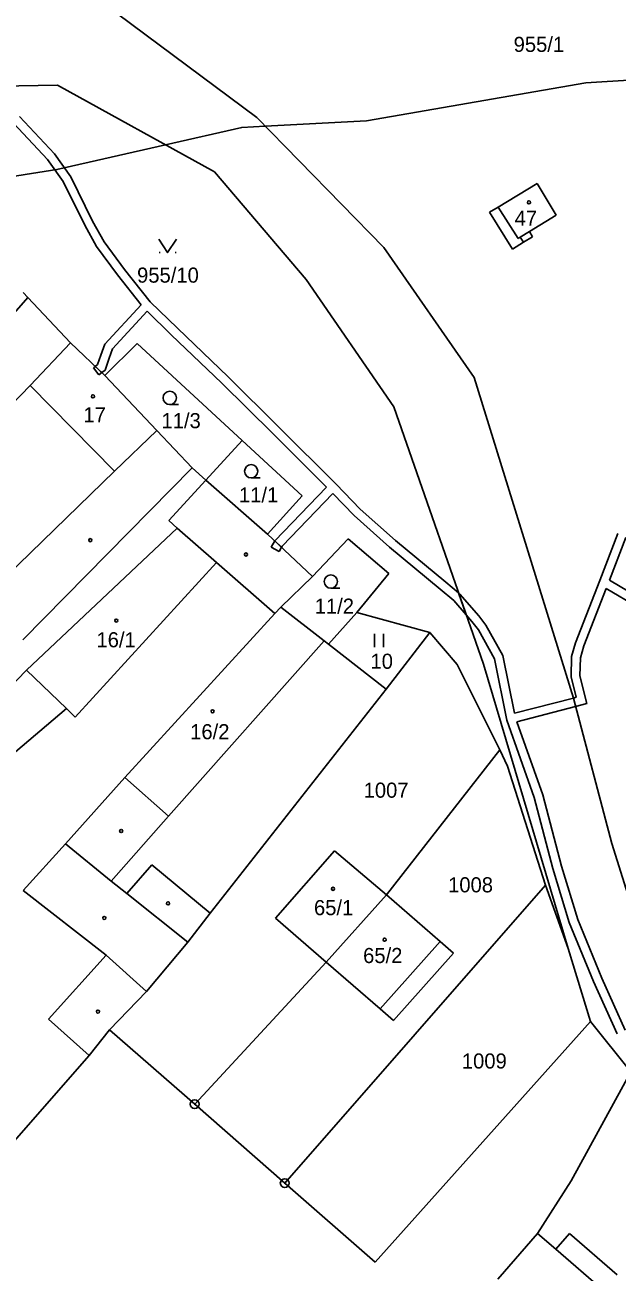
# Model space of a CAD drawing. Extents: x -749173 to -746119, y -1132678 to -1130338.
# Drawn here: x -747893.8 to -747827.1, y -1131098.8 to -1130958.5 of the extents above; entities that cross this region are included whole.
import ezdxf

# ---------------------------------------------------------------- set-up
doc = ezdxf.new("R2010")
doc.units = 0
for name, color, linetype in [('Vrstva 1', 7, 'Continuous'), ('Vrstva 18', 7, 'Continuous'), ('Vrstva 19', 7, 'Continuous'), ('Vrstva 24', 7, 'Continuous'), ('Vrstva 25', 7, 'Continuous'), ('Vrstva 3', 7, 'Continuous'), ('Vrstva 30', 7, 'Continuous'), ('Vrstva 37', 7, 'Continuous'), ('Vrstva 4', 7, 'Continuous'), ('Vrstva 52', 7, 'Continuous')]:
    doc.layers.add(name, color=color, linetype=linetype)

msp = doc.modelspace()

# ---------------------------------------------------------------- linework, layer by layer
at = {"layer": 'Vrstva 1'}
for p, q in [((-747856.43, -1131024.62), (-747848.2, -1131026.86)), ((-747848.2, -1131026.86), (-747853.12, -1131033.24)), ((-747848.2, -1131026.86), (-747845.11, -1131030.47)), ((-747853.12, -1131033.24), (-747859.61, -1131028.15)), ((-747845.11, -1131030.47), (-747840.33, -1131040.05)), ((-747842.17, -1131030.42), (-747832.63, -1131062.43)), ((-747853.12, -1131033.24), (-747872.94, -1131058.46)), ((-747853.09, -1131056.39), (-747840.33, -1131040.05)), ((-747840.33, -1131040.05), (-747839.47, -1131041.9)), ((-747839.47, -1131041.9), (-747835.16, -1131055.31)), ((-747865.56, -1131059.01), (-747858.92, -1131051.41)), ((-747858.92, -1131051.41), (-747853.09, -1131056.39)), ((-747835.16, -1131055.31), (-747864.53, -1131088.83)), ((-747835.16, -1131055.31), (-747832.63, -1131062.43)), ((-747859.86, -1131063.94), (-747853.09, -1131056.39)), ((-747853.09, -1131056.39), (-747847.05, -1131061.64)), ((-747859.86, -1131063.94), (-747865.56, -1131059.01)), ((-747847.05, -1131061.64), (-747845.55, -1131062.96)), ((-747832.63, -1131062.43), (-747830.09, -1131070.64)), ((-747874.67, -1131079.94), (-747859.86, -1131063.94)), ((-747853.8, -1131069.21), (-747859.86, -1131063.94)), ((-747845.55, -1131062.96), (-747852.29, -1131070.52)), ((-747884.28, -1131071.56), (-747880.08, -1131067.26)), ((-747852.29, -1131070.52), (-747853.8, -1131069.21)), ((-747830.09, -1131070.64), (-747854.37, -1131097.71)), ((-747830.09, -1131070.64), (-747825.56, -1131076.31)), ((-747884.28, -1131071.56), (-747886.56, -1131074.48)), ((-747874.67, -1131079.94), (-747884.28, -1131071.56)), ((-747864.53, -1131088.83), (-747874.67, -1131079.94)), ((-747854.37, -1131097.71), (-747864.53, -1131088.83))]:
    msp.add_line(p, q, dxfattribs=at)
for points in [[(-747883.35, -1130957.23), (-747867.68, -1130968.89)], [(-747905.36, -1130965.53), (-747890.11, -1130965.25)], [(-747872.45, -1130974.99), (-747890.11, -1130965.25)], [(-747867.68, -1130968.89), (-747853.38, -1130983.52)], [(-747862.12, -1130987.14), (-747872.45, -1130974.99)], [(-747836.13, -1130976.33), (-747840.51, -1130978.98)], [(-747833.96, -1130979.87), (-747836.13, -1130976.33)], [(-747840.51, -1130978.98), (-747841.46, -1130979.55)], [(-747841.46, -1130979.55), (-747838.9, -1130983.72)], [(-747836.99, -1130981.73), (-747833.96, -1130979.87)], [(-747836.63, -1130982.32), (-747837.64, -1130982.94)], [(-747836.99, -1130981.73), (-747836.63, -1130982.32)], [(-747853.38, -1130983.52), (-747843.2, -1130998.16)], [(-747837.64, -1130982.94), (-747838.9, -1130983.72)], [(-747852.24, -1131001.44), (-747862.12, -1130987.14)], [(-747893.47, -1130989.15), (-747907.26, -1131004.91)], [(-747893.98, -1130988.57), (-747893.47, -1130989.15)], [(-747893.47, -1130989.15), (-747888.65, -1130994.25)], [(-747888.65, -1130994.25), (-747884.79, -1130997.93)], [(-747884.79, -1130997.93), (-747881.15, -1130994.34)], [(-747881.15, -1130994.34), (-747869.31, -1131005.23)], [(-747878.95, -1131004.11), (-747884.79, -1130997.93)], [(-747843.2, -1130998.16), (-747832.03, -1131034.24)], [(-747842.17, -1131030.42), (-747852.24, -1131001.44)], [(-747874.96, -1131008.33), (-747878.95, -1131004.11)], [(-747869.31, -1131005.23), (-747873.4, -1131009.7)], [(-747869.31, -1131005.23), (-747862.56, -1131011.46)], [(-747874.96, -1131008.33), (-747894.04, -1131027.67)], [(-747874.96, -1131008.33), (-747873.4, -1131009.7)], [(-747873.4, -1131009.7), (-747877.57, -1131014.25)], [(-747873.4, -1131009.7), (-747866.49, -1131015.77)], [(-747862.56, -1131011.46), (-747866.49, -1131015.77)], [(-747893.59, -1131031.09), (-747876.64, -1131015.12)], [(-747877.57, -1131014.25), (-747876.64, -1131015.12)], [(-747866.49, -1131015.77), (-747861.39, -1131020.56)], [(-747861.39, -1131020.56), (-747857.4, -1131016.33)], [(-747857.4, -1131016.33), (-747852.82, -1131020.21)], [(-747861.39, -1131020.56), (-747864.99, -1131024.01)], [(-747852.82, -1131020.21), (-747856.43, -1131024.62)], [(-747865.63, -1131024.71), (-747882.52, -1131043.19)], [(-747864.99, -1131024.01), (-747865.63, -1131024.71)], [(-747860.09, -1131027.78), (-747864.99, -1131024.01)], [(-747856.43, -1131024.62), (-747859.61, -1131028.15)], [(-747859.61, -1131028.15), (-747860.09, -1131027.78)], [(-747893.59, -1131031.09), (-747905.46, -1131043.33)], [(-747832.03, -1131034.24), (-747827.69, -1131050.62)], [(-747882.52, -1131043.19), (-747889.22, -1131050.64)], [(-747889.22, -1131050.64), (-747893.98, -1131055.9)], [(-747827.69, -1131050.62), (-747823.07, -1131065.32)], [(-747884.64, -1131063.16), (-747893.98, -1131055.9)], [(-747875.44, -1131061.71), (-747872.94, -1131058.46)], [(-747875.44, -1131061.71), (-747880.08, -1131067.26)], [(-747884.64, -1131063.16), (-747891.12, -1131070.38)], [(-747891.12, -1131070.38), (-747886.56, -1131074.48)], [(-747886.56, -1131074.48), (-747913.2, -1131104.85)], [(-747832.27, -1131088.57), (-747825.56, -1131076.31)], [(-747836.06, -1131094.48), (-747832.27, -1131088.57)], [(-747840.55, -1131099.64), (-747836.06, -1131094.48)], [(-747836.06, -1131094.48), (-747834.02, -1131096.25)], [(-747834.02, -1131096.25), (-747832.48, -1131094.48)], [(-747832.48, -1131094.48), (-747827.12, -1131099.14)]]:
    msp.add_lwpolyline(points, dxfattribs=at)
at = {"layer": 'Vrstva 24'}
for p, q in [((-747874.72, -1131079.94), (-747874.62, -1131079.94)), ((-747864.58, -1131088.83), (-747864.48, -1131088.83))]:
    msp.add_line(p, q, dxfattribs=at)
for centre in [(-747874.67, -1131079.94), (-747864.53, -1131088.83)]:
    msp.add_circle(centre, 0.499, dxfattribs=at)
at = {"layer": 'Vrstva 25'}
for p, q in [((-747878.67, -1130984.09), (-747878.57, -1130984.09)), ((-747876.87, -1130984.09), (-747876.77, -1130984.09)), ((-747877.48, -1131001.2), (-747876.48, -1131001.2)), ((-747868.31, -1131009.46), (-747867.31, -1131009.46)), ((-747859.34, -1131021.87), (-747858.34, -1131021.87)), ((-747854.42, -1131027.02), (-747854.42, -1131028.52)), ((-747853.42, -1131028.52), (-747853.42, -1131027.02))]:
    msp.add_line(p, q, dxfattribs=at)
msp.add_lwpolyline([(-747878.72, -1130982.59), (-747877.72, -1130984.09), (-747876.72, -1130982.59)], dxfattribs=at)
for centre, radius in [((-747837.04, -1130978.44), 0.175), ((-747877.48, -1131000.45), 0.75), ((-747886.13, -1131000.28), 0.175), ((-747868.31, -1131008.71), 0.75), ((-747886.43, -1131016.46), 0.175), ((-747868.9, -1131018.08), 0.175), ((-747859.34, -1131021.12), 0.75), ((-747883.5, -1131025.51), 0.175), ((-747872.66, -1131035.72), 0.175), ((-747882.95, -1131049.2), 0.175), ((-747859.09, -1131055.7), 0.175), ((-747877.67, -1131057.34), 0.175), ((-747884.85, -1131058.98), 0.175), ((-747853.29, -1131061.43), 0.175), ((-747885.56, -1131069.52), 0.175)]:
    msp.add_circle(centre, radius, dxfattribs=at)
at = {"layer": 'Vrstva 3'}
for points in [[(-747836.13, -1130976.33), (-747840.51, -1130978.98)], [(-747833.96, -1130979.87), (-747836.13, -1130976.33)], [(-747840.51, -1130978.98), (-747838.26, -1130982.51)], [(-747836.99, -1130981.73), (-747833.96, -1130979.87)], [(-747838.26, -1130982.51), (-747838.01, -1130982.35)], [(-747838.01, -1130982.35), (-747836.99, -1130981.73)], [(-747893.21, -1130999.04), (-747888.65, -1130994.25)], [(-747888.65, -1130994.25), (-747884.79, -1130997.93)], [(-747878.95, -1131004.11), (-747884.79, -1130997.93)], [(-747883.69, -1131008.71), (-747893.21, -1130999.04)], [(-747883.69, -1131008.71), (-747878.95, -1131004.11)], [(-747893.59, -1131031.09), (-747876.64, -1131015.12)], [(-747876.64, -1131015.12), (-747872.21, -1131018.98)], [(-747872.21, -1131018.98), (-747888.12, -1131036.37)], [(-747865.63, -1131024.71), (-747882.52, -1131043.19)], [(-747864.99, -1131024.01), (-747865.63, -1131024.71)], [(-747860.09, -1131027.78), (-747864.99, -1131024.01)], [(-747860.09, -1131027.78), (-747877.61, -1131047.54)], [(-747889.12, -1131035.41), (-747893.59, -1131031.09)], [(-747888.12, -1131036.37), (-747889.12, -1131035.41)], [(-747882.52, -1131043.19), (-747877.61, -1131047.54)], [(-747865.56, -1131059.01), (-747858.92, -1131051.41)], [(-747858.92, -1131051.41), (-747853.09, -1131056.39)], [(-747859.86, -1131063.94), (-747853.09, -1131056.39)], [(-747859.86, -1131063.94), (-747853.09, -1131056.39)], [(-747853.09, -1131056.39), (-747847.05, -1131061.64)], [(-747859.86, -1131063.94), (-747865.56, -1131059.01)], [(-747853.8, -1131069.21), (-747847.05, -1131061.64)], [(-747853.8, -1131069.21), (-747859.86, -1131063.94)]]:
    msp.add_lwpolyline(points, dxfattribs=at)
at = {"layer": 'Vrstva 30'}
for points in [[(-747894.38, -1130968.79), (-747890.46, -1130972.99)], [(-747891.24, -1130973.63), (-747895.06, -1130969.53)], [(-747890.46, -1130972.99), (-747888.61, -1130975.57)], [(-747889.47, -1130976.09), (-747891.24, -1130973.63)], [(-747888.61, -1130975.57), (-747886.17, -1130980.56)], [(-747887.05, -1130981.02), (-747889.47, -1130976.09)], [(-747885.72, -1130983.42), (-747887.05, -1130981.02)], [(-747886.17, -1130980.56), (-747884.88, -1130982.88)], [(-747884.88, -1130982.88), (-747882.58, -1130986.01)], [(-747883.38, -1130986.61), (-747885.72, -1130983.42)], [(-747880.71, -1130989.97), (-747883.38, -1130986.61)], [(-747882.58, -1130986.01), (-747879.68, -1130989.65)], [(-747879.68, -1130989.65), (-747876.61, -1130992.62)], [(-747884.77, -1130994.4), (-747880.71, -1130989.97)], [(-747880.03, -1130990.7), (-747883.91, -1130994.94)], [(-747877.31, -1130993.34), (-747880.03, -1130990.7)], [(-747876.61, -1130992.62), (-747870.9, -1130998.07)], [(-747871.6, -1130998.79), (-747877.31, -1130993.34)], [(-747885.23, -1130995.63), (-747884.77, -1130994.4)], [(-747883.91, -1130994.94), (-747884.29, -1130995.97)], [(-747886.07, -1130997.06), (-747885.87, -1130996.9)], [(-747885.87, -1130996.9), (-747885.61, -1130996.71)], [(-747885.87, -1130996.9), (-747885.13, -1130997.6)], [(-747885.13, -1130997.6), (-747885.87, -1130996.9)], [(-747885.61, -1130996.71), (-747885.23, -1130995.63)], [(-747884.29, -1130995.97), (-747884.75, -1130997.33)], [(-747885.48, -1130997.86), (-747886.07, -1130997.06)], [(-747885.13, -1130997.6), (-747885.48, -1130997.86)], [(-747884.75, -1130997.33), (-747885.13, -1130997.6)], [(-747870.9, -1130998.07), (-747865.18, -1131003.76)], [(-747865.88, -1131004.46), (-747871.6, -1130998.79)], [(-747865.18, -1131003.76), (-747858.76, -1131010.15)], [(-747859.82, -1131010.51), (-747865.88, -1131004.46)], [(-747865.66, -1131016.55), (-747859.82, -1131010.51)], [(-747858.76, -1131010.15), (-747856.03, -1131012.96)], [(-747859.12, -1131011.22), (-747864.83, -1131017.12)], [(-747856.71, -1131013.68), (-747859.12, -1131011.22)], [(-747852.74, -1131017.26), (-747856.71, -1131013.68)], [(-747856.03, -1131012.96), (-747852.08, -1131016.5)], [(-747866.05, -1131017.26), (-747865.66, -1131016.55)], [(-747865.66, -1131016.55), (-747864.91, -1131017.26)], [(-747864.91, -1131017.26), (-747865.66, -1131016.55)], [(-747852.08, -1131016.5), (-747846.39, -1131021.2)], [(-747829.04, -1131021), (-747827.02, -1131015.71)], [(-747826.12, -1131016.15), (-747827.96, -1131020.96)], [(-747865.17, -1131017.74), (-747866.05, -1131017.26)], [(-747864.91, -1131017.26), (-747865.17, -1131017.74)], [(-747864.83, -1131017.12), (-747864.91, -1131017.26)], [(-747847.03, -1131021.98), (-747852.74, -1131017.26)], [(-747845.5, -1131023.24), (-747847.03, -1131021.98)], [(-747846.39, -1131021.2), (-747844.96, -1131022.4)], [(-747831.79, -1131028.02), (-747829.04, -1131021)], [(-747828.33, -1131021.91), (-747830.85, -1131028.34)], [(-747821.21, -1131026.12), (-747828.33, -1131021.91)], [(-747827.96, -1131020.96), (-747820.69, -1131025.26)], [(-747844.1, -1131024.86), (-747845.5, -1131023.24)], [(-747844.96, -1131022.4), (-747844.8, -1131022.53)], [(-747844.1, -1131024.86), (-747844.96, -1131022.4)], [(-747844.96, -1131022.4), (-747844.1, -1131024.86)], [(-747844.8, -1131022.53), (-747842.68, -1131024.98)], [(-747843.46, -1131025.6), (-747844.1, -1131024.86)], [(-747842.68, -1131024.98), (-747841.89, -1131026.02)], [(-747842.73, -1131026.57), (-747843.46, -1131025.6)], [(-747841.89, -1131026.02), (-747839.96, -1131029.46)], [(-747840.9, -1131029.82), (-747842.73, -1131026.57)], [(-747832.24, -1131029.54), (-747831.79, -1131028.02)], [(-747830.85, -1131028.34), (-747831.24, -1131029.69)], [(-747839.51, -1131036.71), (-747840.9, -1131029.82)], [(-747839.96, -1131029.46), (-747838.65, -1131035.92)], [(-747832.3, -1131031.84), (-747832.24, -1131029.54)], [(-747831.24, -1131029.69), (-747831.3, -1131031.74)], [(-747831.73, -1131034.14), (-747832.3, -1131031.84)], [(-747831.3, -1131031.74), (-747830.53, -1131034.84)], [(-747838.65, -1131035.92), (-747832.03, -1131034.24)], [(-747832.03, -1131034.24), (-747831.73, -1131034.14)], [(-747832.03, -1131034.24), (-747831.78, -1131035.19)], [(-747831.78, -1131035.19), (-747832.03, -1131034.24)], [(-747831.78, -1131035.19), (-747838.39, -1131036.89)], [(-747830.53, -1131034.84), (-747831.78, -1131035.19)], [(-747836.45, -1131045.43), (-747839.51, -1131036.71)], [(-747838.39, -1131036.89), (-747835.49, -1131045.13)], [(-747834.35, -1131053.42), (-747836.45, -1131045.43)], [(-747835.49, -1131045.13), (-747833.39, -1131053.14)], [(-747832.49, -1131059.48), (-747834.35, -1131053.42)], [(-747833.39, -1131053.14), (-747831.55, -1131059.14)], [(-747829.76, -1131066.15), (-747832.49, -1131059.48)], [(-747831.55, -1131059.14), (-747828.84, -1131065.77)], [(-747827.11, -1131072.04), (-747829.76, -1131066.15)], [(-747828.84, -1131065.77), (-747826.21, -1131071.62)]]:
    msp.add_lwpolyline(points, dxfattribs=at)
at = {"layer": 'Vrstva 37'}
for centre in [(-747837.04, -1130978.44), (-747886.13, -1131000.28), (-747883.5, -1131025.51), (-747872.66, -1131035.72), (-747859.09, -1131055.7), (-747853.29, -1131061.43)]:
    msp.add_circle(centre, 0.175, dxfattribs=at)
at = {"layer": 'Vrstva 4'}
msp.add_line((-747853.8, -1131069.21), (-747847.05, -1131061.64), dxfattribs=at)
for points in [[(-747840.51, -1130978.98), (-747838.26, -1130982.51)], [(-747838.26, -1130982.51), (-747838.01, -1130982.35)], [(-747838.01, -1130982.35), (-747836.99, -1130981.73)], [(-747838.01, -1130982.35), (-747837.64, -1130982.94)], [(-747893.21, -1130999.04), (-747888.65, -1130994.25)], [(-747893.21, -1130999.04), (-747902.85, -1131008.98)], [(-747883.69, -1131008.71), (-747893.21, -1130999.04)], [(-747883.69, -1131008.71), (-747878.95, -1131004.11)], [(-747898.59, -1131023.13), (-747883.69, -1131008.71)], [(-747876.64, -1131015.12), (-747872.21, -1131018.98)], [(-747872.21, -1131018.98), (-747888.12, -1131036.37)], [(-747872.21, -1131018.98), (-747865.63, -1131024.71)], [(-747860.09, -1131027.78), (-747877.61, -1131047.54)], [(-747889.12, -1131035.41), (-747893.59, -1131031.09)], [(-747889.12, -1131035.41), (-747902.13, -1131046.44)], [(-747888.12, -1131036.37), (-747889.12, -1131035.41)], [(-747882.52, -1131043.19), (-747877.61, -1131047.54)], [(-747877.61, -1131047.54), (-747884.09, -1131054.83)], [(-747884.09, -1131054.83), (-747889.22, -1131050.64)], [(-747879.51, -1131053.02), (-747882.32, -1131056.24)], [(-747879.51, -1131053.02), (-747872.94, -1131058.46)], [(-747882.32, -1131056.24), (-747884.09, -1131054.83)], [(-747875.44, -1131061.71), (-747882.32, -1131056.24)], [(-747884.64, -1131063.16), (-747880.08, -1131067.26)], [(-747834.02, -1131096.25), (-747828.66, -1131100.91)]]:
    msp.add_lwpolyline(points, dxfattribs=at)
at = {"layer": 'Vrstva 52'}
msp.add_lwpolyline([(-747807.18, -1130963.67), (-747807.69, -1130963.62), (-747825.18, -1130964.67), (-747830.62, -1130965), (-747855.31, -1130969.25), (-747866.73, -1130969.86), (-747869.37, -1130970), (-747877.95, -1130971.96), (-747890.19, -1130974.75), (-747897.57, -1130975.89), (-747898.25, -1130976), (-747904.91, -1130977.89), (-747921.73, -1130982.67), (-747937.37, -1130987.12), (-747943.37, -1130989.25), (-747945.09, -1130990.33), (-747946.75, -1130991.37), (-747956.65, -1130995.11), (-747964.08, -1130997.92), (-747965.94, -1130998.62), (-747967.99, -1130999.4), (-747987.69, -1131006.84)], dxfattribs=at)

# ---------------------------------------------------------------- texts
at = {"layer": 'Vrstva 18'}
for s, p in [('955/1', (-747838.76, -1130961.51)), ('955/10', (-747881.16, -1130987.48)), ('11/3', (-747878.41, -1131003.86)), ('11/1', (-747869.69, -1131012.22)), ('11/2', (-747861.16, -1131024.74)), ('10', (-747854.88, -1131030.94)), ('1007', (-747855.65, -1131045.45)), ('1008', (-747846.14, -1131056.1)), ('1009', (-747844.59, -1131075.93))]:
    msp.add_text(s, height=1.7, dxfattribs=at).set_placement(p)
at = {"layer": 'Vrstva 19'}
for s, p in [('47', (-747838.65, -1130981.07)), ('17', (-747887.2, -1131003.2)), ('16/1', (-747885.73, -1131028.52)), ('16/2', (-747875.18, -1131038.87)), ('65/1', (-747861.24, -1131058.67)), ('65/2', (-747855.71, -1131064.06))]:
    msp.add_text(s, height=1.7, dxfattribs=at).set_placement(p)

doc.saveas('drawing.dxf')
